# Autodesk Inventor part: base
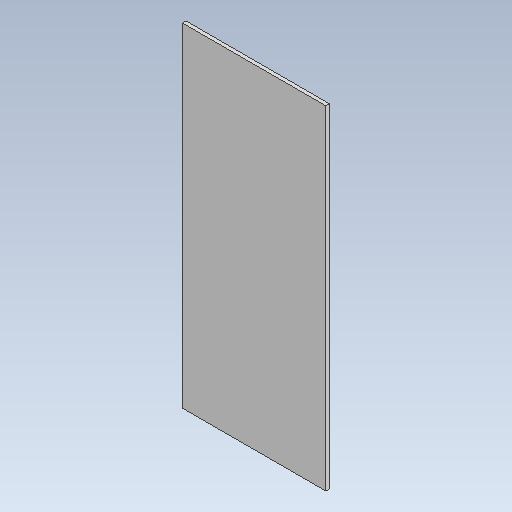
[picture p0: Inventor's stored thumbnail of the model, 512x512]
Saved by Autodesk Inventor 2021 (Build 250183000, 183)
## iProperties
Created: 2026-10
Part Number: base
Material: Generic
Document SubType Name: Modeling
Designer: alolo
Density: 1 g/cm^3
Appearance: Default
Author: alolo
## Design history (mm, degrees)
sketch "Sketch1"
  geometry: L1 (0, 0)-(200, 0); L2 (200, 0)-(200, 465); L3 (200, 465)-(0, 465); L4 (0, 465)-(0, 0)
  constraints: 8 end point, 2 parallel, 1 horizontal, 1 perpendicular
  dimensions: "d0" = 200 distance of L3.end L2.end; "d1" = 465 distance of L2.end L1.end
extrude "Extrusion1" new body sketch "Sketch1" distance "d2" = 5 (= wood_thickness); taper "d3" = 0 deg
body "Solid1"
other parameters: "slide_length" = 195 [user parameter], "slide_angle" = 7 deg [user parameter], "slide_width" = 65 [user parameter], "wood_thickness" = 5 [user parameter; used in 1 equation term], "aclyric_thickness" = 6 [user parameter]
